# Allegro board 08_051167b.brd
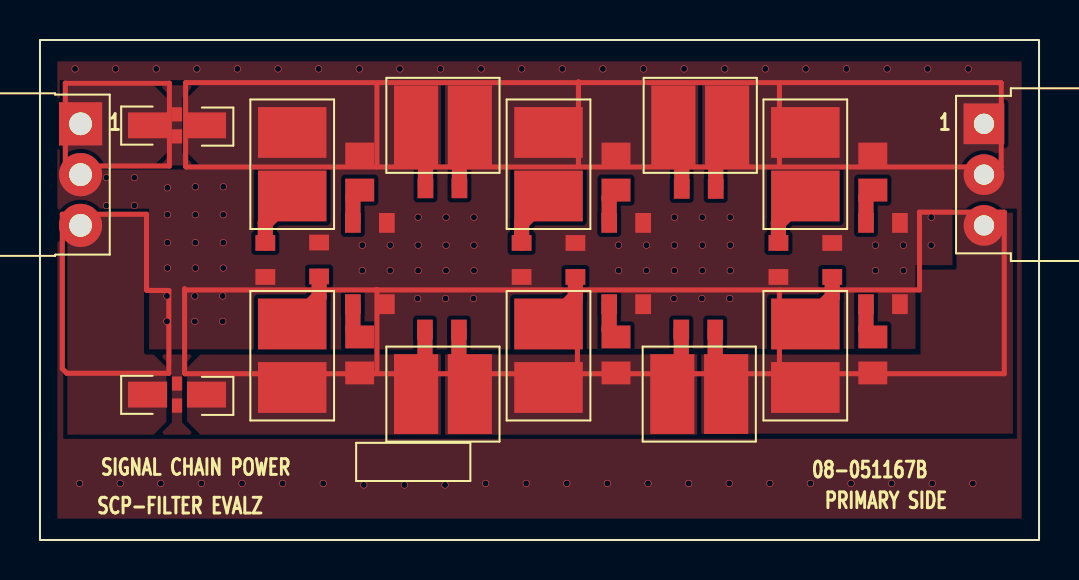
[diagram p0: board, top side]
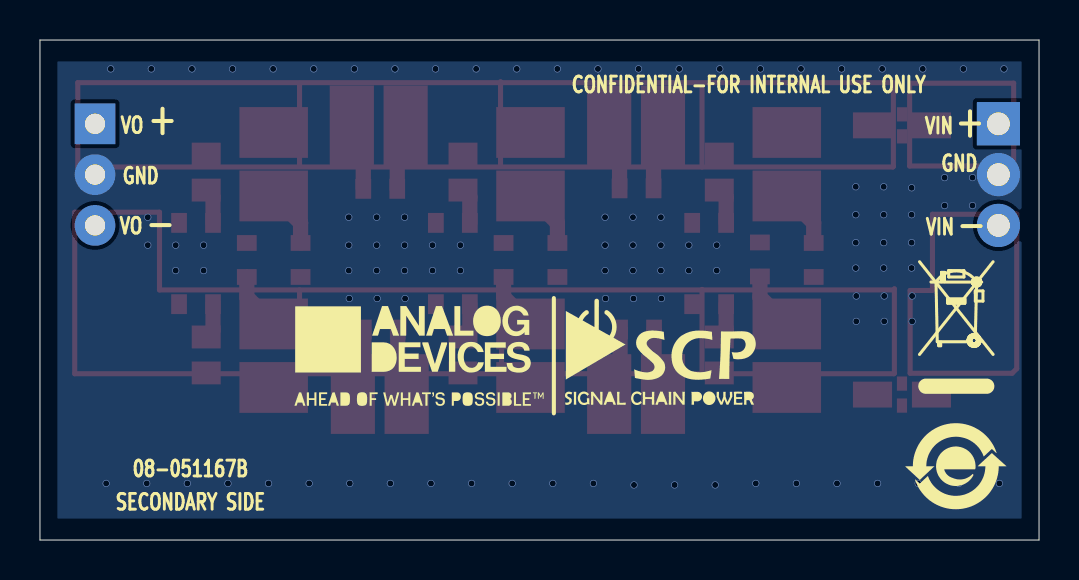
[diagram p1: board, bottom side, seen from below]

Outline 50 x 25 mm; copper layers: TOP, L2_FILLER, L3_FILLER, BOTTOM. Coordinates in mm from the lower left corner of the outline.
Outline path: 0,25 50,25 50,0 0,0 0,25

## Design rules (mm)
constraint set DEFAULT: min track width 0.203

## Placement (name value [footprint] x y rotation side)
C1  GEN_0603_0805_1206  [GEN0603_0805_1206]  6.86 20.73 0 top
C2  GEN_0603_0805_1206  [GEN0603_0805_1206]  6.86 7.27 0 top
C3  GEN_C1812_1210_1206_0805  [C1812_1210_1206_0805]  12.62 18.79 90 top
C4  GEN_C1812_1210_1206_0805  [C1812_1210_1206_0805]  12.62 9.21 90 top
C5  GEN_C1812_1210_1206_0805  [C1812_1210_1206_0805]  25.45 18.79 90 top
C6  GEN_C1812_1210_1206_0805  [C1812_1210_1206_0805]  25.45 9.21 90 top
C7  GEN_C1812_1210_1206_0805  [C1812_1210_1206_0805]  38.3 18.79 90 top
C8  GEN_C1812_1210_1206_0805  [C1812_1210_1206_0805]  38.3 9.21 90 top
C9  TBD0805  [C0805]  16 18.4 270 top
C10  TBD0805  [C0805]  16 9.25 270 top
C11  TBD0805  [C0805]  28.83 18.4 270 top
C12  TBD0805  [C0805]  28.83 9.25 270 top
C13  TBD0805  [C0805]  41.68 18.4 270 top
C14  TBD0805  [C0805]  41.68 9.25 270 top
INPUT  PBC03SBAN  [CNTHMHDRRA1X3L300W100H145]  2.03 20.81 270 top
L1  -  [L0603_0805_1206_0806_LSMSQ157]  20.17 20.73 0 top
L2  -  [L0603_0805_1206_0806_LSMSQ157]  20.17 7.3 0 top
L3  -  [L0603_0805_1206_0806_LSMSQ157]  33.05 20.73 0 top
L4  -  [L0603_0805_1206_0806_LSMSQ157]  32.99 7.3 0 top
NOREF  -  []  2.03 20.81 0 top
NOREF#2  -  []  25.51 46.03 0 top
NOREF#3  -  []  90.79 32.31 0 top
NOREF#4  -  []  -197.25 -222.03 0 top
NOREF#5  -  []  50 0 90 top
NOREF#6  -  []  -131.19 155.48 0 top
NOREF#7  -  []  50 25 180 top
NOREF#8  -  []  0 0 0 top
NOREF#9  -  []  -197.25 -222.03 0 top
NOREF#10  -  []  44.53 3.99 0 top
NOREF#11  -  []  50 0 90 top
NOREF#12  -  []  0 25 0 top
NOREF#13  -  []  77.05 131.34 0 top
NOREF#14  -  []  50 25 0 top
NOREF#15  -  []  0 0 0 top
NOREF#16  -  []  2.03 20.81 0 top
NOREF#17  -  []  0 25 0 top
NOREF#18  -  []  0 25 270 top
NOREF#19  -  []  -137.31 -48.38 0 top
NOREF#20  -  []  -197.25 -222.03 0 top
NOREF#21  -  []  0 25 0 top
NOREF#22  -  []  4.34 7.37 180 bottom
NOREF#23  -  []  18.92 9.4 180 bottom
NOREF#24  -  []  4.17 3.69 180 bottom
NOREF#25  -  []  17.55 11.26 180 bottom
NOREF#26  -  []  31.32 9.18 180 bottom
OUTPUT  PPPC031LGBN-RC  [CNHDRRA1X3H108]  47.24 20.81 270 top
R1  0  [R0603]  11.28 14 270 top
R2  0  [R0603]  13.97 14.03 270 top
R3  0  [R0603]  24.1 14 270 top
R4  0  [R0603]  26.8 14 270 top
R5  0  [R0603]  36.96 14 270 top
R6  0  [R0603]  39.65 14 270 top
R7  0  [R0603]  16.51 15.86 0 top
R8  0  [R0603]  16.51 11.79 180 top
R9  0  [R0603]  20.14 17.58 0 top
R10  0  [R0603]  20.12 10.52 0 top
R11  0  [R0603]  32.97 17.56 0 top
R12  0  [R0603]  32.94 10.52 0 top
R13  0  [R0603]  29.34 15.86 0 top
R14  0  [R0603]  29.34 11.79 180 top
R15  0  [R0603]  42.19 15.86 0 top
R16  0  [R0603]  42.19 11.79 180 top

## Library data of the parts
C1 C2 = GEN4P_CAP: User Part Number: UPN; Tolerance: N/A; alternate symbols: (); part number: GEN4P_CAP_SM-GEN_0603_0805_1206,E034170,GEN0603_0805_1206; tolerance: N/A
C3-C8 = GEN_CAP: Tolerance: N/A; User Part Number: UPN; alternate symbols: (); part number: GEN_CAP_SM-GEN_C1812_1210_1206_0805,E034112,C1812_1210_1206_0805; tolerance: N/A
C9-C14 = CAP: User Part Number: UPN; alternate symbols: (); part number: CAP_SM-TBD0805,TBD0805,TBD0805,E000383,C0805
INPUT = CN3P: Tolerance: N/A; User Part Number: UPN; alternate symbols: (CNTHMHDRRA1X3L300W100H145_SCP); part number: CN3P_TH-PBC03SBAN,E034137,CNTHMHDRRA1X3L300W100H145; tolerance: N/A
L1-L4 = GEN_IND: Tolerance: N/A; User Part Number: UPN; alternate symbols: (); part number: GEN_IND_SM-L0603_0805_1206_0806_LSMSQ157,E034114,L0603_0805_1206_0806_LSMSQ157; tolerance: N/A
OUTPUT = CN3P: User Part Number: UPN; Tolerance: N/A; alternate symbols: (CNHDRRA1X3H108_SCP); part number: CN3P_TH-PPPC031LGBN-RC,E034111,CNHDRRA1X3H108; tolerance: N/A
R1-R16 = RES: User Part Number: UPN; Tolerance: N/A; alternate symbols: (R0603L); part number: RES_SM-0,E005803,N/A,N/A,R0603; tolerance: N/A

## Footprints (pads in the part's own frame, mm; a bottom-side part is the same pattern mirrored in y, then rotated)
C0805
  rect 1.143x1.448 smd: 1(-0.9,0) 2(0.9,0)
C1812_1210_1206_0805
  rect 2.54x3.429 smd: 1(-1.587,0) 2(1.587,0)
CNHDRRA1X3H108
  rect 2.032x2.032 hole 1.016: 1(0,0)
  round 2.032 hole 1.016: 2(2.54,0) 3(5.08,0)
CNTHMHDRRA1X3L300W100H145
  rect 2.159x2.159 hole 1.143: 1(0,0)
  round 2.159 hole 1.143: 2(2.54,0) 3(5.08,0)
GEN0603_0805_1206
  rect 1.956x1.295 smd: 1(-1.475,0) 2(1.475,0)
  rect 0.508x0.711 smd: 3(0,-0.55) 4(0,0.55)
L0603_0805_1206_0806_LSMSQ157
  rect 2.21x3.988 smd: 1(-1.346,0) 2(1.346,0)
R0603
  rect 0.787x0.991 smd: 1(-0.85,0) 2(0.85,0)

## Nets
AGND: INPUT.2 OUTPUT.2 R1.2(N2) R2.1 R3.2(N2) R4.1 R5.2(N2) R6.1 R7.2(N2) R8.1 R13.2(N2) R14.1 R15.2(N2) R16.1
GND1: C1.3 C1.4(N4)
GND2: C2.3 C2.4(N4)
UNNAMED_2_CAP_I136_N2: C9.2(N2) R7.1
UNNAMED_2_CAP_I138_N1: C10.1 R8.2(N2)
UNNAMED_2_CAP_I139_N1: C12.1 R14.2(N2)
UNNAMED_2_CAP_I141_N1: C14.1 R16.2(N2)
UNNAMED_2_CAP_I144_N2: C11.2(N2) R13.1
UNNAMED_2_CAP_I146_N2: C13.2(N2) R15.1
UNNAMED_2_GEN4PCAP_I25_N2: C1.2 C3.2(N2) C9.1 L1.1 R9.1
UNNAMED_2_GEN4PCAP_I26_N2: C2.2 C4.1 C10.2(N2) L2.1 R10.1
UNNAMED_2_GENCAP_I98_N1: C3.1 R1.1
UNNAMED_2_GENCAP_I99_N2: C4.2(N2) R2.2(N2)
UNNAMED_2_GENCAP_I100_N1: C6.1 C12.2(N2) L2.2(N2) L4.1 R10.2(N2) R12.1
UNNAMED_2_GENCAP_I100_N2: C6.2(N2) R4.2(N2)
UNNAMED_2_GENCAP_I101_N2: C8.2(N2) R6.2(N2)
UNNAMED_2_GENCAP_I104_N1: C7.1 R5.1
UNNAMED_2_GENCAP_I105_N1: C5.1 R3.1
UNNAMED_2_GENCAP_I105_N2: C5.2(N2) C11.1 L1.2(N2) L3.1 R9.2(N2) R11.1
V+: C1.1 INPUT.1
V-: C2.1 INPUT.3(N3)
VO+: C7.2(N2) C13.1 L3.2(N2) OUTPUT.1 R11.2(N2)
VO-: C8.1 C14.2(N2) L4.2(N2) OUTPUT.3(N3) R12.2(N2)

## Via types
v1: diameter 0.356, hole 0.305, TOP to BOTTOM, 106 vias

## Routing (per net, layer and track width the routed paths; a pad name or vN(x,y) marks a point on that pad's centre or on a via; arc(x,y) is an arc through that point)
AGND: length 0
  vias: v1(1.76,23.55) v1(1.98,2.83) v1(3.33,18.12) v1(3.33,16.72) v1(3.79,23.55) v1(4.02,2.83) v1(4.73,18.12) v1(4.73,16.72) v1(5.82,23.55) v1(6.05,2.83) v1(6.38,17.61) v1(6.38,16.27) v1(6.38,14.87) v1(6.38,13.6) v1(6.35,12.2) v1(6.35,10.93) v1(7.77,17.66) v1(7.77,16.27) v1(7.77,14.87) v1(7.77,13.6) v1(7.75,12.2) v1(7.75,10.93) v1(7.85,23.55) v1(8.08,2.83) v1(9.17,17.66) v1(9.17,16.27) v1(9.17,14.87) v1(9.17,13.6) v1(9.15,12.2) v1(9.15,10.93) v1(9.88,23.55) v1(10.11,2.83) v1(11.92,23.55) v1(12.14,2.83) v1(13.95,23.55) v1(14.18,2.83) v1(15.98,23.55) v1(16.13,14.74) v1(16.13,13.47) v1(16.21,2.75) v1(17.53,14.74) v1(17.53,13.47) v1(18.01,23.55) v1(18.24,2.75) v1(18.93,16.14) v1(18.93,14.74) v1(18.93,13.47) v1(18.9,12.07) v1(20.04,23.55) v1(20.27,2.75) v1(20.32,16.14) v1(20.32,14.74) v1(20.32,13.47) v1(20.3,12.07) v1(21.72,16.14) v1(21.72,14.74) v1(21.72,13.47) v1(21.69,12.07) v1(22.08,23.55) v1(22.3,2.83) v1(24.11,23.55) v1(24.34,2.83) v1(26.14,23.55) v1(26.37,2.83) v1(28.17,23.55) v1(28.4,2.83) v1(28.96,14.74) v1(28.96,13.47) v1(30.2,23.55) v1(30.36,14.74) v1(30.36,13.47) v1(30.43,2.83) v1(31.75,16.14) v1(31.75,14.74) v1(31.75,13.47) v1(31.73,12.07) v1(32.24,23.55) v1(32.46,2.83) v1(33.15,16.14) v1(33.15,14.74) v1(33.15,13.47) v1(33.12,12.07) v1(34.27,23.55) v1(34.55,16.14) v1(34.55,14.74) v1(34.55,13.47) v1(34.52,12.07) v1(34.5,2.83) v1(36.3,23.55) v1(36.53,2.83) v1(38.33,23.55) v1(38.56,2.83) v1(40.36,23.55) v1(40.59,2.83) v1(41.81,14.74) v1(41.81,13.47) v1(42.4,23.55) v1(42.62,2.83) v1(43.21,14.74) v1(43.21,13.47) v1(44.43,23.55) v1(44.6,16.14) v1(44.6,14.74) v1(44.66,2.83) v1(46.46,23.55) v1(46.69,2.83)
UNNAMED_2_CAP_I136_N2: length 1.8
  TOP w0.762: C9.2 15.66,17.15 R7.1
UNNAMED_2_CAP_I138_N1: length 1.8
  TOP w0.762: C10.1 15.66,10.49 R8.2
UNNAMED_2_CAP_I139_N1: length 1.8
  TOP w0.762: C12.1 28.49,10.49 R14.2
UNNAMED_2_CAP_I141_N1: length 1.8
  TOP w0.762: R16.2 41.34,10.49 C14.1
UNNAMED_2_CAP_I144_N2: length 1.8
  TOP w0.762: R13.1 28.49,17.15 C11.2
UNNAMED_2_CAP_I146_N2: length 1.8
  TOP w0.762: C13.2 41.34,17.15 R15.1
UNNAMED_2_GEN4PCAP_I25_N2: length 3.3
  TOP w0.762: R9.1 19.29,20.26 L1.1
UNNAMED_2_GEN4PCAP_I26_N2: length 3.4
  TOP w0.762: R10.1 19.27,7.74 L2.1
UNNAMED_2_GENCAP_I98_N1: length 2.9
  TOP w0.762: C3.1 11.28,15.86 R1.1
UNNAMED_2_GENCAP_I99_N2: length 2.9
  TOP w0.762: C4.2 13.97,12.15 R2.2
UNNAMED_2_GENCAP_I100_N1: length 6.9
  TOP w0.762: L4.1 32.09,7.74 R12.1 ; R10.2 20.97,7.84 L2.2
UNNAMED_2_GENCAP_I100_N2: length 2.9
  TOP w0.762: C6.2 26.8,12.15 R4.2
UNNAMED_2_GENCAP_I101_N2: length 2.9
  TOP w0.762: C8.2 39.65,12.15 R6.2
UNNAMED_2_GENCAP_I104_N1: length 2.9
  TOP w0.762: R5.1 36.96,15.86 C7.1
UNNAMED_2_GENCAP_I105_N1: length 2.9
  TOP w0.762: R3.1 24.1,15.86 C5.1
UNNAMED_2_GENCAP_I105_N2: length 6.7
  TOP w0.762: R9.2 20.99,20.21 L1.2 ; R11.1 32.12,20.31 L3.1
VO+: length 3.4
  TOP w0.762: R11.2 33.82,20.16 L3.2
VO-: length 3.5
  TOP w0.762: L4.2 33.79,7.84 R12.2

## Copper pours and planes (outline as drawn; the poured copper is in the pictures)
AGND on TOP: 0.87,23.93 49.13,23.93 49.13,1.07 0.87,1.07 ; 2 cut-outs
AGND on BOTTOM: 0.87,1.07 0.87,23.93 49.13,23.93 49.13,1.07
GND1 on TOP: 5.99,18.73 6.6,19.34 6.6,22.12 5.98,22.74 7.72,22.74 7.11,22.14 7.11,19.34 7.72,18.73
GND2 on TOP: 5.99,5.26 6.6,5.87 6.6,8.65 5.98,9.28 7.72,9.28 7.11,8.67 7.11,5.87 7.72,5.26
UNNAMED_2_GEN4PCAP_I25_N2 on TOP: 7.42,22.74 20.07,22.74 20.07,18.73 7.42,18.73
UNNAMED_2_GEN4PCAP_I26_N2 on TOP: 8.03,9.28 20.07,9.28 20.07,5.26 8.03,5.26 7.37,5.92 7.37,8.62
UNNAMED_2_GENCAP_I100_N1 on TOP: 20.27,9.28 32.89,9.28 32.89,5.26 20.27,5.26
UNNAMED_2_GENCAP_I105_N2 on TOP: 20.27,22.74 32.94,22.74 32.94,18.73 20.27,18.73
V+ on TOP: 1.19,22.74 6.35,22.74 6.35,18.73 1.22,18.73
V- on TOP: 1.37,16.34 5.21,16.34 5.21,9.35 5.28,9.28 5.69,9.28 6.32,8.64 6.32,5.9 5.69,5.26 1.37,5.26
VO+ on TOP: 33.15,22.74 47.98,22.74 47.98,18.73 33.15,18.73
VO- on TOP: 45.87,16.36 48.69,16.36 48.69,5.32 33.1,5.32 33.1,9.28 44.07,9.28 44.07,13.52 45.8,13.52 45.87,13.6

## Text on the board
Ref Des/Silkscreen Bottom: GND | VIN | CONFIDENTIAL-FOR INTERNAL USE ONLY | 08-051167B | VO | - | +
User.Comments: 4.    RoHS COMPLIANCE: ASSEMBLY VENDOR SHOULD ASSURE COMPLIANCE | WITH LEAD-FREE AND RoHS PCB ASSEMBLY STANDARDS (EU RoHS | DIRECTIVE 2002/95/EC).
Ref Des/Silkscreen Top: SCP-FILTER EVALZ | SIGNAL CHAIN POWER
ROOT_NUMBER: 051167
PAGE_OUTLINE: N/A | A.CAUILAN | K.JABATAN | J.M.PLAZA | J.VIERNES | E.CONDA | 05DEC18 | A | B | AS PER ECR-086428 | 08MAY19 | SCP-FILTER EVALZ | EVALUATION BOARD | -051167
DIMENSION: REF | SEE FAB NOTES 15 | DIA MAX
User.15: ROHS COMPLIANCE NOTE:  (Required for Customer Boards) Add to top of MATERIALS | ENIG (Electroless Nickel/Immersion Gold) | PER IPC-4552 LATEST REVISION | HOMOGENOUS MATERIALS IN THIS BOARD SHALL BE COMPLIANT | THE EU RoHS DIRECTIVE 2002/95/EC | INTERNAL LAYERS .5 OZ. COPPER. | 15.    THRU VIAS TO BE FILLED WITH SOLDERMASK.
User.17: L2 FILLER | 08-      -07
User.18: L3 FILLER | 08-      -08
User.23: 1 | B
User.27: 2 | B
User.45: 2 | FIGURE | SIZE | 12.0 | 40.0 | 45.0 | PLATED | FINISHED HOLES IN MILS | ALL UNITS ARE IN MILS | QTY | 106 | 3 | TOLERANCE/NOTES | EVALUATION BOARD | B
